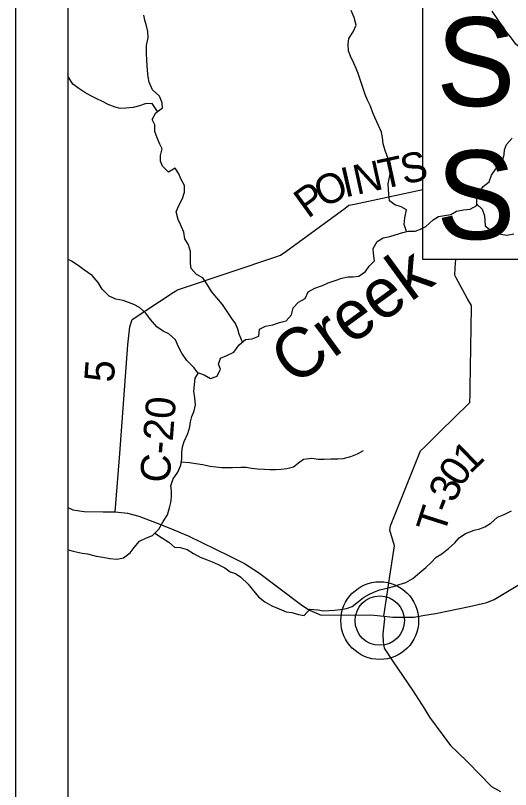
# Model space of a CAD drawing. Extents: x 0 to 34, y 0 to 22.
# Drawn here: x 2 to 2.947, y 14.793 to 16.276 of the extents above; entities that cross this region are included whole.
import ezdxf

# ---------------------------------------------------------------- set-up
doc = ezdxf.new("R2010")
doc.units = 0
for name, color, linetype in [('GM_X_County_Road', 7, 'Continuous'), ('GM_X_County_Road_Text', 7, 'Continuous'), ('GM_X_Minor_River', 7, 'Continuous'), ('GM_X_Minor_River_Text', 7, 'Continuous'), ('GM_X_Township_Road', 7, 'Continuous'), ('GM_X_Township_Road_Text', 7, 'Continuous'), ('GM_X_Unincorporated', 7, 'Continuous'), ('GM_X_Unincorporated_Location', 7, 'Continuous'), ('SH_Data', 7, 'Continuous'), ('SH_Text', 7, 'Continuous')]:
    doc.layers.add(name, color=color, linetype=linetype)

msp = doc.modelspace()

# ---------------------------------------------------------------- linework, layer by layer
at = {"layer": 'GM_X_County_Road'}
for points in [[(2.191, 15.3255), (2.1996, 15.4371), (2.215, 15.6452), (2.2188, 15.6794), (2.2233, 15.6939), (2.3017, 15.7451), (2.3099, 15.7502), (2.3197, 15.7535), (2.5001, 15.8143), (2.5071, 15.8166), (2.5173, 15.8241), (2.6306, 15.9069), (2.638, 15.9123), (2.6485, 15.9146), (2.7795, 15.9429)], [(2.1, 15.3338), (2.11, 15.3293), (2.1312, 15.3259), (2.168, 15.3252), (2.191, 15.3255)], [(2.191, 15.3255), (2.2146, 15.3227), (2.2358, 15.3172), (2.2712, 15.3036), (2.2955, 15.2942), (2.3306, 15.279), (2.4091, 15.2409), (2.438, 15.2261), (2.4652, 15.2091), (2.5479, 15.1465), (2.5628, 15.1369), (2.5849, 15.1273), (2.6801, 15.1278), (2.7049, 15.1251), (2.7059, 15.1205), (2.703, 15.0914), (2.7035, 15.0755), (2.7056, 15.0638), (2.7226, 15.0377), (2.7596, 14.9836), (2.7829, 14.9479), (2.7926, 14.932), (2.8324, 14.8777), (2.8464, 14.8641), (2.8656, 14.8459), (2.911, 14.7991), (2.9279, 14.7897)]]:
    msp.add_lwpolyline(points, dxfattribs=at)
at = {"layer": 'GM_X_Minor_River'}
msp.add_line((2.1, 15.2523), (2.1007, 15.2522), dxfattribs=at)
for points in [[(2.7483, 15.862), (2.7438, 15.8756), (2.745, 15.8885), (2.7481, 15.9036), (2.7383, 15.9097), (2.7258, 15.9132), (2.716, 15.9212), (2.7145, 15.9337), (2.7138, 15.9432), (2.7135, 15.9534), (2.7158, 15.9663), (2.7181, 15.9795), (2.717, 15.9928), (2.7114, 16.0065), (2.7073, 16.0171), (2.7039, 16.0304), (2.7024, 16.0425), (2.7002, 16.0524), (2.695, 16.0653), (2.6886, 16.0793), (2.6841, 16.0892), (2.6792, 16.1021), (2.6739, 16.1135), (2.6695, 16.1249), (2.6646, 16.1382), (2.6605, 16.1515), (2.6556, 16.1648), (2.6519, 16.1746), (2.6474, 16.1845), (2.6414, 16.1982), (2.6376, 16.208), (2.6365, 16.2209), (2.6381, 16.2319), (2.6464, 16.2444), (2.6518, 16.2573), (2.6484, 16.2721), (2.6421, 16.2857)], [(3.023, 16.0936), (3.0182, 16.1118), (3.0194, 16.1247), (3.0156, 16.1357), (3.0123, 16.1464), (3.0085, 16.1589), (3.0071, 16.1684), (3.0052, 16.1809), (2.9954, 16.1923), (2.9822, 16.201), (2.972, 16.2087), (2.9577, 16.2209), (2.949, 16.2323), (2.9385, 16.2456), (2.9313, 16.2562), (2.9219, 16.2699), (2.9125, 16.2843)], [(2.4345, 15.6503), (2.4279, 15.6653), (2.4253, 15.6751), (2.4212, 15.6858), (2.414, 15.6953), (2.4054, 15.7089), (2.3963, 15.7222), (2.385, 15.7352), (2.3749, 15.7473), (2.3677, 15.7599), (2.3583, 15.7732), (2.3462, 15.7797), (2.3364, 15.7911), (2.335, 15.8009), (2.335, 15.8104), (2.3347, 15.8237), (2.3309, 15.8366), (2.3242, 15.8484), (2.3223, 15.8609), (2.316, 15.8757), (2.3111, 15.8852), (2.3077, 15.9), (2.3123, 15.9121), (2.3195, 15.9257), (2.3234, 15.9378), (2.3234, 15.9503), (2.3163, 15.9629), (2.3129, 15.9727), (2.3058, 15.9838), (2.2925, 15.9759), (2.2812, 15.9876), (2.2774, 15.9971), (2.2775, 16.0077), (2.2805, 16.0202), (2.2764, 16.0297), (2.2712, 16.0419), (2.2667, 16.054), (2.2667, 16.0665), (2.2615, 16.0768), (2.2683, 16.0897), (2.2812, 16.0991), (2.2805, 16.1086), (2.2756, 16.1215), (2.2624, 16.1333), (2.2561, 16.1481), (2.2538, 16.1587), (2.2524, 16.1705), (2.252, 16.1799), (2.2513, 16.1909), (2.251, 16.2027), (2.2506, 16.2186), (2.2537, 16.2338), (2.2534, 16.2451), (2.2504, 16.2558), (2.2474, 16.2668), (2.2456, 16.2766)], [(2.2715, 16.092), (2.2616, 16.1075), (2.248, 16.1068), (2.2374, 16.1027), (2.2249, 16.0997), (2.2112, 16.0982), (2.2006, 16.0979), (2.1908, 16.1002), (2.1776, 16.1052), (2.1666, 16.1109), (2.1557, 16.1162), (2.1444, 16.122), (2.1327, 16.1281), (2.121, 16.1361), (2.11, 16.1441), (2.1017, 16.1581), (2.1, 16.1629)], [(2.9361, 16.0189), (2.9396, 16.0287), (2.9506, 16.0412)], [(2.1007, 15.2522), (2.1105, 15.2499), (2.1279, 15.246), (2.1377, 15.2445), (2.1547, 15.2406), (2.1672, 15.2383), (2.1804, 15.2356), (2.1937, 15.2348), (2.2065, 15.237), (2.2194, 15.2468), (2.2274, 15.2567), (2.2373, 15.2688), (2.2506, 15.2751), (2.2623, 15.2796), (2.2741, 15.2917), (2.2828, 15.3069), (2.2908, 15.3197), (2.2946, 15.3326), (2.297, 15.3428), (2.2985, 15.353), (2.2986, 15.3656), (2.2975, 15.375), (2.302, 15.3883), (2.3108, 15.4011), (2.3165, 15.4148), (2.3181, 15.4265), (2.3181, 15.4386), (2.3197, 15.4496), (2.3227, 15.4598), (2.3296, 15.4754), (2.3338, 15.4882), (2.335, 15.4977), (2.3377, 15.5075), (2.3419, 15.5189), (2.3446, 15.5299), (2.3431, 15.5435), (2.3413, 15.5564), (2.3428, 15.5693), (2.344, 15.5814), (2.3501, 15.5913), (2.361, 15.5874), (2.3731, 15.5809), (2.386, 15.5851), (2.3921, 15.5983), (2.3884, 15.6078), (2.3922, 15.6195), (2.4047, 15.6244), (2.4176, 15.6308), (2.4278, 15.6448), (2.4404, 15.655), (2.4532, 15.6565), (2.4657, 15.6617), (2.4669, 15.6754), (2.4787, 15.681), (2.4927, 15.6832), (2.5055, 15.6877), (2.5177, 15.6911), (2.5279, 15.7028), (2.5314, 15.7157), (2.5416, 15.727), (2.5541, 15.7338), (2.5602, 15.7463), (2.5731, 15.7538), (2.5875, 15.759), (2.5985, 15.7636), (2.614, 15.7688), (2.6246, 15.7726), (2.6364, 15.7755), (2.6462, 15.7755), (2.6568, 15.7766), (2.6701, 15.7856), (2.6766, 15.7955), (2.6868, 15.8057), (2.6853, 15.8205), (2.6846, 15.8299), (2.6919, 15.8432), (2.7036, 15.8503), (2.7165, 15.8529), (2.7263, 15.8559), (2.7415, 15.86), (2.7517, 15.863), (2.7646, 15.863), (2.7752, 15.8664), (2.785, 15.872), (2.7991, 15.8848), (2.8093, 15.8909), (2.8207, 15.8931), (2.8332, 15.895), (2.8442, 15.9014), (2.8574, 15.9036), (2.8699, 15.9047), (2.8828, 15.9122), (2.8832, 15.9228), (2.8859, 15.9353), (2.895, 15.9485), (2.9068, 15.9576), (2.911, 15.9701), (2.919, 15.9822), (2.9307, 15.9943), (2.935, 16.009), (2.9361, 16.0189)], [(2.8829, 15.9145), (2.8933, 15.905), (2.8978, 15.8924), (2.8982, 15.8826), (2.8989, 15.8731), (2.9121, 15.8624), (2.9253, 15.8575), (2.9401, 15.8551), (2.9537, 15.8577)], [(2.3497, 15.5907), (2.3414, 15.6019), (2.3282, 15.6152), (2.3184, 15.6289), (2.3121, 15.6411), (2.3064, 15.6547), (2.2936, 15.6662), (2.2827, 15.6715), (2.2706, 15.6795), (2.2582, 15.6936), (2.2495, 15.7057), (2.2374, 15.7164), (2.2265, 15.7221), (2.2163, 15.7263), (2.2061, 15.7298), (2.1921, 15.7325), (2.1793, 15.7386), (2.1657, 15.7519), (2.1582, 15.7645), (2.1465, 15.7778), (2.1299, 15.7896), (2.1201, 15.7968), (2.1072, 15.8052), (2.1, 15.8092)], [(2.3173, 15.421), (2.3332, 15.4196), (2.3453, 15.4177), (2.3578, 15.4161), (2.3725, 15.413), (2.3835, 15.4111), (2.3952, 15.4103), (2.4156, 15.4102), (2.4315, 15.4105), (2.4413, 15.4105), (2.4519, 15.4089), (2.4633, 15.4078), (2.4765, 15.407), (2.4867, 15.4065), (2.4973, 15.4061), (2.5087, 15.4068), (2.5193, 15.4079), (2.5318, 15.4117), (2.5416, 15.4192), (2.5511, 15.426), (2.567, 15.4278), (2.5802, 15.4259), (2.5908, 15.4259), (2.6033, 15.4266), (2.6166, 15.4265), (2.6268, 15.4276), (2.6419, 15.4313), (2.6548, 15.4366), (2.6662, 15.4426)], [(2.2667, 15.2842), (2.2816, 15.275), (2.2933, 15.267), (2.3046, 15.2575), (2.3152, 15.2567), (2.3288, 15.2529), (2.3405, 15.2456), (2.3533, 15.2387), (2.3665, 15.233), (2.3764, 15.2296), (2.3869, 15.225), (2.4009, 15.2181), (2.4111, 15.2105), (2.4213, 15.207), (2.4315, 15.1998), (2.4451, 15.1869), (2.453, 15.1773), (2.465, 15.1621), (2.4771, 15.1526), (2.4903, 15.145), (2.5043, 15.1393), (2.5179, 15.1339), (2.5288, 15.1327), (2.5413, 15.1285), (2.5526, 15.1269), (2.5633, 15.1387), (2.5784, 15.1378), (2.5897, 15.1359), (2.6, 15.1362), (2.6106, 15.137), (2.6219, 15.1381), (2.6333, 15.1403), (2.6446, 15.144), (2.6564, 15.1535), (2.6663, 15.161), (2.6765, 15.167), (2.686, 15.1715), (2.6966, 15.1757), (2.711, 15.179), (2.7235, 15.1824), (2.7344, 15.1861), (2.7469, 15.1899), (2.7606, 15.1978), (2.7735, 15.2091), (2.7856, 15.2189), (2.7955, 15.2284), (2.805, 15.2386), (2.816, 15.245), (2.8289, 15.2548), (2.8407, 15.2657), (2.8494, 15.2755), (2.8612, 15.2835), (2.8775, 15.2902), (2.8884, 15.2928), (2.8983, 15.2962), (2.91, 15.3037), (2.9222, 15.3147), (2.9354, 15.3203), (2.9491, 15.3271)]]:
    msp.add_lwpolyline(points, dxfattribs=at)
at = {"layer": 'GM_X_Township_Road'}
msp.add_line((2.8417, 15.7929), (2.843, 15.8085), dxfattribs=at)
for points in [[(2.8702, 15.5633), (2.8724, 15.7167), (2.8724, 15.7202), (2.8653, 15.7332), (2.8434, 15.7735), (2.8406, 15.7787), (2.8416, 15.7911), (2.8417, 15.7929)], [(2.8122, 15.4783), (2.8685, 15.5336), (2.8698, 15.5348), (2.87, 15.5514), (2.8702, 15.5606), (2.8702, 15.5633)], [(2.7049, 15.1251), (2.7085, 15.1511), (2.7177, 15.2105), (2.7254, 15.2601), (2.7162, 15.2902), (2.7177, 15.2986), (2.7213, 15.3077), (2.7725, 15.4356), (2.775, 15.4418), (2.7833, 15.45), (2.8095, 15.4757), (2.8122, 15.4783)], [(2.7049, 15.1251), (2.722, 15.1232), (2.7629, 15.1234), (2.7795, 15.1268), (2.8035, 15.1306), (2.8687, 15.1436), (2.9019, 15.1513), (2.9158, 15.1571), (3.0566, 15.2417)]]:
    msp.add_lwpolyline(points, dxfattribs=at)
at = {"layer": 'GM_X_Unincorporated'}
for radius in [0.0744, 0.0472]:
    msp.add_circle((2.6971, 15.1168), radius, dxfattribs=at)
at = {"layer": 'GM_X_Unincorporated_Location'}
msp.add_line((2.6971, 15.1168), (2.6971, 15.1168), dxfattribs=at)
at = {"layer": 'SH_Data'}
for p, q in [((2, 21), (2, 14)), ((2.1, 20.9), (2.1, 14.1))]:
    msp.add_line(p, q, dxfattribs=at)
at = {"layer": 'SH_Text'}
msp.add_lwpolyline([(2.7795, 16.5585), (4.7911, 16.5585), (4.7911, 15.8085), (2.7795, 15.8085)], close=True, dxfattribs=at)

# ---------------------------------------------------------------- texts
at = {"layer": 'GM_X_County_Road_Text'}
for s, height, rotation, p in [('S', 0.0568, 12.3012, (2.7433, 15.952)), ('N', 0.0568, 12.3237, (2.653, 15.9322)), ('T', 0.0568, 12.2992, (2.7018, 15.9429)), ('I', 0.0568, 12.7659, (2.6303, 15.9271)), ('O', 0.0568, 25.3463, (2.5882, 15.9068)), ('P', 0.0568, 35.72, (2.5595, 15.8858)), ('5', 0.0568, 85.917, (2.188, 15.5719)), ('C-20', 0.05682, 85.5458, (2.2946, 15.3795))]:
    msp.add_text(s, height=height, rotation=rotation, dxfattribs=at).set_placement(p)
at = {"layer": 'GM_X_Minor_River_Text'}
msp.add_text('Creek', height=0.0947, rotation=36.0028, dxfattribs=at).set_placement((2.5335, 15.5646))
at = {"layer": 'GM_X_Township_Road_Text'}
for s, rotation, p in [('1', 44.1819, (2.8702, 15.3966)), ('0', 55.9098, (2.8527, 15.3702)), ('3', 68.1979, (2.8413, 15.3408)), ('-', 68.1977, (2.8327, 15.3193)), ('T', 72.2182, (2.8201, 15.2799))]:
    msp.add_text(s, height=0.0568, rotation=rotation, dxfattribs=at).set_placement(p)
at = {"layer": 'SH_Text'}
for s, p in [('STA. 551+25.00', (2.8051, 16.1024)), ('SLM 10.44', (2.8051, 15.8474))]:
    msp.add_text(s, height=0.17, dxfattribs=at).set_placement(p)

doc.saveas('drawing.dxf')
